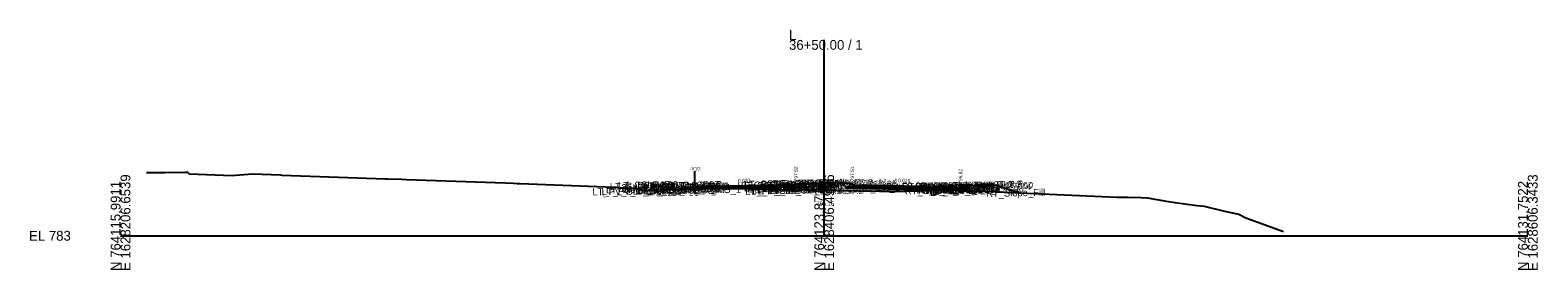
# Model space of a CAD drawing. Extents: x -26 to 4403, y -510 to 9556.
# Drawn here: x 1974.3 to 2402.8, y 6490.3 to 6558.5 of the extents above; entities that cross this region are included whole.
import ezdxf

# ---------------------------------------------------------------- set-up
doc = ezdxf.new("R2010")
doc.units = 0
for name, color, linetype in [('Default', 7, 'Continuous'), ('Exist CMT Pavement', 7, 'Continuous'), ('Exist Cross Section Cell', 7, 'Continuous'), ('Exist XS Center Line Elevation Label', 7, 'Continuous'), ('Exist XS Ground Line', 7, 'Continuous'), ('Prop CMT Conc Surface', 7, 'Continuous'), ('Prop CMT Concrete Structures', 7, 'Continuous'), ('Prop CMT Pvmt Course 1', 7, 'Continuous'), ('Prop CMT Pvmt Course 1 CG', 7, 'Continuous'), ('Prop CMT Pvmt Course 2', 7, 'Continuous'), ('Prop CMT Pvmt Course 2 Wedge', 7, 'Continuous'), ('Prop CMT Pvmt Course 3', 7, 'Continuous'), ('Prop CMT Pvmt Course 3 Wedge', 7, 'Continuous'), ('Prop CMT Pvmt Surface', 7, 'Continuous'), ('Prop CMT Shear Line', 7, 'Continuous'), ('Prop CMT Slope Grass', 7, 'Continuous'), ('Prop CMT Subgrade Earthwork', 7, 'Continuous'), ('Prop XS Hydro Elevations', 7, 'Continuous'), ('Prop XS SE Text', 7, 'Continuous'), ('Prop XS Side Slope Text', 7, 'Continuous'), ('Scratch_Level_0', 7, 'Continuous')]:
    doc.layers.add(name, color=color, linetype=linetype)

msp = doc.modelspace()

# ---------------------------------------------------------------- linework, layer by layer
at = {"layer": 'Exist CMT Pavement'}
for points in [[(2149.17, 6512.8), (2149.17, 6512.8)], [(2163.25, 6513.49), (2168.84, 6513.49), (2172.17, 6513.49), (2178.81, 6513.36), (2181.92, 6513.29), (2184.79, 6513.19), (2191.01, 6512.97)]]:
    msp.add_lwpolyline(points, dxfattribs=at)
at = {"layer": 'Exist Cross Section Cell'}
for p, q in [((2200, 6500), (2200, 6555.73)), ((2000, 6500), (2200, 6500)), ((2200, 6500), (2400, 6500))]:
    msp.add_line(p, q, dxfattribs=at)
at = {"layer": 'Exist XS Ground Line'}
msp.add_lwpolyline([(2007.4, 6518.01), (2009.83, 6517.99), (2012.55, 6518.02), (2018.43, 6518.07), (2019.07, 6518.08), (2019.5, 6517.6), (2031.72, 6517.19), (2032.64, 6517.22), (2037.51, 6517.63), (2045.44, 6517.34), (2045.83, 6517.3), (2075.31, 6516.22), (2075.88, 6516.24), (2079.96, 6516.09), (2081.23, 6516.07), (2109.3, 6515.09), (2111.72, 6515), (2112.75, 6514.92), (2113.69, 6514.93), (2140.22, 6513.86), (2141.88, 6513.71), (2142.76, 6513.63), (2145.75, 6513.46), (2146.57, 6513.36), (2147.7, 6513.2), (2149.17, 6512.8), (2153.86, 6513.2), (2161.74, 6513.49), (2168.84, 6513.49), (2172.17, 6513.49), (2178.81, 6513.36), (2181.92, 6513.29), (2184.79, 6513.19), (2191.01, 6512.97), (2191.68, 6512.81), (2193.69, 6513.16), (2194.85, 6513.28), (2195.83, 6513.08), (2197.69, 6513.29), (2200, 6513.16), (2203.87, 6512.94), (2215.7, 6512.73), (2223.11, 6512.71), (2226.5, 6512.76), (2236.53, 6513.05), (2237.9, 6513.05), (2248.98, 6512.55), (2283.26, 6510.95), (2286.4, 6511.04), (2289.98, 6510.94), (2291.91, 6510.83), (2297.21, 6509.9), (2299.76, 6509.52), (2305.9, 6508.64), (2307.97, 6508.43), (2313.75, 6507.01), (2317.89, 6506.15), (2319.84, 6505.14), (2330.56, 6501.18)], dxfattribs=at)
at = {"layer": 'Prop CMT Conc Surface'}
for points in [[(2191.25, 6514.5), (2192, 6514.51), (2192, 6514.68), (2192.76, 6514.93)], [(2208.75, 6514.5), (2208, 6514.51), (2208, 6514.68), (2207.24, 6514.93)], [(2236.75, 6513.94), (2238.75, 6513.82)], [(2238.75, 6513.82), (2238.75, 6514.32), (2239.25, 6514.32)], [(2243.25, 6514.41), (2248.25, 6514.51)]]:
    msp.add_lwpolyline(points, dxfattribs=at)
at = {"layer": 'Prop CMT Concrete Structures'}
for points in [[(2163.25, 6513.36), (2163.25, 6513.94)], [(2191.25, 6514.5), (2192, 6514.51), (2192, 6514.68), (2192.76, 6514.93)], [(2191.25, 6513.92), (2191.25, 6514.5)], [(2192.76, 6513.95), (2191.25, 6513.92)], [(2192.76, 6514.93), (2192.76, 6513.95)], [(2208.75, 6514.5), (2208, 6514.51), (2208, 6514.68), (2207.24, 6514.93)], [(2207.24, 6514.93), (2207.24, 6513.95)], [(2207.24, 6513.95), (2208.75, 6513.92)], [(2208.75, 6513.92), (2208.75, 6514.5)], [(2236.75, 6513.94), (2238.75, 6513.82), (2238.75, 6514.32), (2239.25, 6514.32)], [(2239.25, 6514.32), (2239.25, 6513.31), (2236.75, 6513.36)], [(2236.75, 6513.36), (2236.75, 6513.94)], [(2248.25, 6514.51), (2243.25, 6514.41)], [(2243.25, 6514.41), (2243.25, 6514.08)], [(2243.25, 6514.08), (2248.25, 6514.18)], [(2248.25, 6514.18), (2248.25, 6514.51)]]:
    msp.add_lwpolyline(points, dxfattribs=at)
at = {"layer": 'Prop CMT Pvmt Course 1'}
for points in [[(2191.25, 6514.5), (2163.25, 6513.94)], [(2163.25, 6513.69), (2191.01, 6514.24), (2191.25, 6514.25)], [(2163.25, 6513.94), (2163.25, 6513.69), (2163.25, 6513.69)], [(2191.25, 6514.25), (2191.25, 6514.5)], [(2208.75, 6514.5), (2236.75, 6513.94)], [(2208.75, 6514.25), (2208.75, 6514.5)], [(2236.75, 6513.69), (2208.75, 6514.25)], [(2208.75, 6514.25), (2208.75, 6514.25), (2208.75, 6514.25)], [(2236.75, 6513.94), (2236.75, 6513.69)]]:
    msp.add_lwpolyline(points, dxfattribs=at)
at = {"layer": 'Prop CMT Pvmt Course 1 CG'}
for points in [[(2191.25, 6513.92), (2193.26, 6513.96), (2193.59, 6513.63)], [(2191.25, 6513.58), (2191.25, 6513.92)], [(2208.75, 6513.92), (2206.74, 6513.96), (2206.41, 6513.63)], [(2208.75, 6513.58), (2208.75, 6513.92)], [(2163.25, 6513.02), (2163.25, 6513.36)], [(2193.59, 6513.63), (2191.25, 6513.58)], [(2206.41, 6513.63), (2208.75, 6513.58)], [(2236.75, 6513.36), (2239.75, 6513.3), (2240.09, 6512.96)], [(2236.75, 6513.02), (2236.75, 6513.36)], [(2240.09, 6512.96), (2236.75, 6513.02)]]:
    msp.add_lwpolyline(points, dxfattribs=at)
at = {"layer": 'Prop CMT Pvmt Course 2'}
for points in [[(2191.01, 6514.24), (2191.01, 6513.91)], [(2191.25, 6514.25), (2191.01, 6514.24)], [(2191.01, 6513.91), (2191.25, 6513.92)], [(2191.25, 6513.92), (2191.25, 6514.25)], [(2208.75, 6513.92), (2208.75, 6514.25)], [(2208.75, 6514.25), (2236.75, 6513.69)], [(2236.75, 6513.36), (2208.75, 6513.92)], [(2163.25, 6513.36), (2163.25, 6513.36), (2163.25, 6513.69), (2163.25, 6513.69)], [(2163.25, 6513.69), (2163.25, 6513.36)], [(2236.75, 6513.69), (2236.75, 6513.36)]]:
    msp.add_lwpolyline(points, dxfattribs=at)
at = {"layer": 'Prop CMT Pvmt Course 2 Wedge'}
for points in [[(2163.25, 6513.69), (2168.84, 6513.8), (2172.17, 6513.87), (2178.81, 6514), (2181.92, 6514.06), (2184.79, 6514.12), (2191.01, 6514.24), (2191.01, 6514.24)], [(2191.01, 6513.91), (2191.01, 6513.91), (2184.79, 6513.79), (2181.92, 6513.73), (2178.81, 6513.67), (2172.17, 6513.53), (2170.12, 6513.49), (2168.84, 6513.49), (2163.25, 6513.49)], [(2191.01, 6514.24), (2191.01, 6513.91)], [(2163.25, 6513.49), (2163.25, 6513.69)]]:
    msp.add_lwpolyline(points, dxfattribs=at)
at = {"layer": 'Prop CMT Pvmt Course 3'}
for points in [[(2191.25, 6513.92), (2191.01, 6513.91)], [(2191.01, 6513.91), (2191.01, 6513.58)], [(2191.25, 6513.58), (2191.25, 6513.92)], [(2208.75, 6513.92), (2236.75, 6513.36)], [(2208.75, 6513.58), (2208.75, 6513.92)], [(2163.25, 6513.36), (2163.25, 6513.36), (2163.25, 6513.02), (2163.25, 6513.02)], [(2163.25, 6513.02), (2163.25, 6513.36)], [(2191.01, 6513.58), (2191.25, 6513.58)], [(2236.75, 6513.02), (2208.75, 6513.58)], [(2236.75, 6513.36), (2236.75, 6513.02)]]:
    msp.add_lwpolyline(points, dxfattribs=at)
at = {"layer": 'Prop CMT Pvmt Course 3 Wedge'}
for points in [[(2172.17, 6513.54), (2178.81, 6513.67), (2181.92, 6513.73), (2184.79, 6513.79), (2191.01, 6513.91), (2191.01, 6513.91)], [(2191.01, 6513.91), (2191.01, 6512.97)], [(2170.1, 6513.49), (2172.17, 6513.54)], [(2191.01, 6512.97), (2191.01, 6512.97), (2184.79, 6513.19), (2181.92, 6513.29), (2178.81, 6513.36), (2172.17, 6513.49), (2170.1, 6513.49)]]:
    msp.add_lwpolyline(points, dxfattribs=at)
at = {"layer": 'Prop CMT Pvmt Surface'}
for points in [[(2191.25, 6514.5), (2163.25, 6513.94)], [(2208.75, 6514.5), (2236.75, 6513.94)]]:
    msp.add_lwpolyline(points, dxfattribs=at)
at = {"layer": 'Prop CMT Shear Line'}
msp.add_line((2163.25, 6512.13), (2163.25, 6518.4), dxfattribs=at)
at = {"layer": 'Prop CMT Slope Grass'}
for points in [[(2192.76, 6514.93), (2200, 6515.08)], [(2207.24, 6514.93), (2200, 6515.08)], [(2239.25, 6514.32), (2248.75, 6514.51), (2255.55, 6512.24)]]:
    msp.add_lwpolyline(points, dxfattribs=at)
at = {"layer": 'Prop CMT Subgrade Earthwork'}
for points in [[(2194.93, 6514.97), (2193.59, 6513.63)], [(2205.07, 6514.97), (2206.41, 6513.63)], [(2236.75, 6513.02), (2240.09, 6512.96), (2241.5, 6514.36)], [(2163.25, 6513.02), (2163.25, 6513.36)], [(2163.25, 6513.02), (2163.25, 6513.02)], [(2163.25, 6513.02), (2163.25, 6513.02)], [(2191.25, 6513.58), (2191.01, 6513.58)], [(2191.01, 6513.58), (2191.01, 6512.97)], [(2193.59, 6513.63), (2191.25, 6513.58)], [(2191.25, 6513.58), (2191.25, 6513.58)], [(2206.41, 6513.63), (2208.75, 6513.58)], [(2208.75, 6513.58), (2236.75, 6513.02)], [(2208.75, 6513.58), (2208.75, 6513.58)], [(2208.75, 6513.58), (2208.75, 6513.58)], [(2236.75, 6513.02), (2236.75, 6513.02)]]:
    msp.add_lwpolyline(points, dxfattribs=at)

# ---------------------------------------------------------------- texts
at = {"layer": 'Default'}
msp.add_text('-', height=0.0001, dxfattribs=at).set_placement((2000, 6500))
at = {"layer": 'Exist Cross Section Cell'}
for s, p in [('L', (2190, 6555.73)), ('36+50.00 / 1', (2190, 6552.93)), ('EL 783', (1974, 6498.6))]:
    msp.add_text(s, height=2.8, dxfattribs=at).set_placement(p)
for s, p in [('N 764115.9911', (2000, 6490)), ('E 1628206.6539', (2002.8, 6490)), ('N 764123.8716', (2200, 6490)), ('E 1628406.4986', (2202.8, 6490)), ('N 764131.7522', (2400, 6490)), ('E 1628606.3433', (2402.8, 6490))]:
    msp.add_text(s, height=2.8, rotation=90, dxfattribs=at).set_placement(p)
at = {"layer": 'Exist XS Center Line Elevation Label'}
msp.add_text('796.16', height=1.2, dxfattribs=at).set_placement((2197.78, 6508.56))
at = {"layer": 'Prop XS Hydro Elevations'}
for s, rotation, p in [('-Y10-', 360, (2161.79, 6518.59)), ('797.52', 90, (2192.5, 6515.51)), ('797.51', 90, (2208.5, 6515.51)), ('796.82', 90, (2239.25, 6514.82))]:
    msp.add_text(s, height=1, rotation=rotation, dxfattribs=at).set_placement(p)
at = {"layer": 'Prop XS SE Text'}
for rotation, p in [(1.1458, (2175.48, 6515.18)), (358.8542, (2221.02, 6515.25))]:
    msp.add_text('0.020', height=1, rotation=rotation, dxfattribs=at).set_placement(p)
at = {"layer": 'Prop XS Side Slope Text'}
msp.add_text('3:1', height=1, rotation=341.5683, dxfattribs=at).set_placement((2251.64, 6514.34))
at = {"layer": 'Scratch_Level_0'}
for s, p in [('LT_PV_Sub_Tie_Out', (2134.14, 6511.5)), ('LT_PV_OEEOP_EG', (2136.74, 6511.55)), ('LT_Slope_Fill', (2137.97, 6512.05)), ('LT_Sub_Trench_Out_DLT', (2139.09, 6512.98)), ('LT_CSLP_Pnt', (2141.44, 6513.31)), ('36+50.00', (2142.4, 6512.68)), ('LT_CG1_Shelf_Out', (2146.82, 6512.03)), ('36+50.00', (2147.32, 6513.32)), ('LT_CG_Top_Face', (2148.53, 6513.07)), ('LT_CG_Top_BOC', (2149.05, 6513.09)), ('LT_CG_Bot_BOC', (2149.09, 6512.07)), ('LT_Sub_OEOT_CG_1', (2149.49, 6511.75)), ('LT_CG_Top_Gut', (2149.51, 6512.58)), ('LT_Sub_OEOP', (2150.04, 6511.76)), ('LT_Sub_OEOP', (2150.04, 6511.76)), ('LT_Sub_OEEOP', (2152.48, 6511.81)), ('LT_PV2_OEEOP', (2152.58, 6512.48)), ('LT_PV3_OEEOP', (2152.58, 6512.14)), ('LT_CG_Bot_IE', (2153.18, 6512.16)), ('LT_Sub_OEOT', (2153.35, 6511.82)), ('LT_PV2_OEOT', (2153.44, 6512.49)), ('LT_PV3_OEOT', (2153.44, 6512.16)), ('36+50.00', (2154.03, 6513.18)), ('LT_PV1_OEOT', (2154.01, 6512.76)), ('LT_CG_Top_Face_Med', (2175.39, 6513.35)), ('LT_CG_Top_Gut_Med', (2176.37, 6513.2)), ('LT_CG_Top_BOC_Med', (2177.18, 6513.62)), ('LT_CG_Bot_BOC_Med', (2177.21, 6512.64)), ('LT_CG_Bot_IE_Med', (2177.34, 6512.64)), ('LT_PV_Sub_Tie_In', (2177.6, 6511.7)), ('LT_Sub_IEOT_CG_1', (2178.14, 6512.32)), ('LT_PV_IEEOP_EG', (2179.22, 6511.73)), ('LT_Sub_IEEOP', (2180.89, 6512.38)), ('LT_PV2_IEEOP', (2180.98, 6513.04)), ('LT_PV3_IEEOP', (2180.98, 6512.71)), ('LT_CG1_Shelf_In', (2181.46, 6512.72)), ('LT_Sub_PGL', (2182.39, 6512.41)), ('LT_PV2_PGL', (2182.48, 6513.07)), ('LT_PV3_PGL', (2182.48, 6512.74)), ('LT_PV1_PGL', (2183.05, 6513.34)), ('LT_Sub_DLT_In', (2183.9, 6513.75)), ('LT_Sub_IEOP', (2184.36, 6512.45)), ('36+50.00', (2184.67, 6513.37)), ('MD_Crown Point', (2187.09, 6513.82)), ('36+50.00', (2187.74, 6513.83)), ('RT_CG_Top_Face_Med', (2191.34, 6513.35)), ('RT_CG_Top_BOC_Med', (2191.61, 6513.62)), ('RT_CG_Bot_BOC_Med', (2191.64, 6512.63)), ('RT_CG_Top_Gut_Med', (2192.32, 6513.2)), ('RT_Sub_DLT_In', (2193.99, 6513.75)), ('RT_CG_Bot_IE_Med', (2194.79, 6512.64)), ('RT_CG1_Shelf_In', (2194.89, 6512.72)), ('RT_Sub_IEOT_CG_1', (2195.59, 6512.32)), ('36+50.00', (2195.81, 6513.89)), ('RT_Sub_IEOP', (2197.14, 6512.44)), ('RT_Sub_OEEOP', (2197.94, 6512.37)), ('RT_PV2_OEEOP', (2198.03, 6513.04)), ('RT_PV3_OEEOP', (2198.03, 6512.7)), ('RT_Sub_IEEOP', (2198.58, 6512.38)), ('RT_PV2_IEEOP', (2198.68, 6513.05)), ('RT_Sub_PGL', (2199.84, 6512.4)), ('36+50.00', (2199.99, 6513.81)), ('RT_PV2_PGL', (2199.94, 6513.07)), ('RT_PV1_PGL', (2200.5, 6513.33)), ('36+50.00', (2201.43, 6513.37)), ('36+50.00', (2217.67, 6513.05)), ('RT_Sub_Trench_Out_DLT', (2222.04, 6512.98)), ('RT_Sub_OEOT_CG_1', (2222.95, 6511.75)), ('RT_CG_Top_Face', (2225.99, 6513.06)), ('RT_CG1_Shelf_Out', (2226.28, 6512.03)), ('RT_CG_Bot_IE', (2226.64, 6512.15)), ('RT_Sub_OEOT', (2226.8, 6511.82)), ('RT_PV2_OEOT', (2226.9, 6512.49)), ('RT_PV3_OEOT', (2226.9, 6512.16)), ('RT_CG_Top_Gut', (2226.96, 6512.58)), ('RT_PV1_OEOT', (2227.46, 6512.75)), ('RT_CG_Top_BOC', (2227.51, 6513.08)), ('RT_CG_Bot_BOC', (2227.54, 6512.07)), ('RT_Sub_OEOP', (2230.18, 6511.76)), ('36+50.00', (2230.79, 6512.75)), ('RT_SDWK_In_Top', (2231.08, 6513.17)), ('RT_SDWK_In_Bot', (2231.11, 6512.83)), ('36+50.00', (2231.97, 6512.93)), ('36+50.00', (2232.32, 6513.18)), ('36+50.00', (2233.61, 6513.21)), ('RT_SDWK_Out_Top', (2234.46, 6513.23)), ('RT_SDWK_Out_Bot', (2234.49, 6512.9)), ('RT_CSLP_Pnt', (2238.9, 6513.31)), ('36+50.00', (2245.55, 6512.18)), ('RT_Slope_Fill', (2246.04, 6511.05))]:
    msp.add_text(s, height=2, rotation=1.1458, dxfattribs=at).set_placement(p)

doc.saveas('drawing.dxf')
